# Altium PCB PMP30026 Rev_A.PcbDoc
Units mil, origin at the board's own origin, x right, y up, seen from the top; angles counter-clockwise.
Board outline 2370 x 2370 mil, 2 copper layers (Top Layer, Bottom Layer), stack 62 mil thick; 53 components, 28 nets, 107 pads, 37 vias.
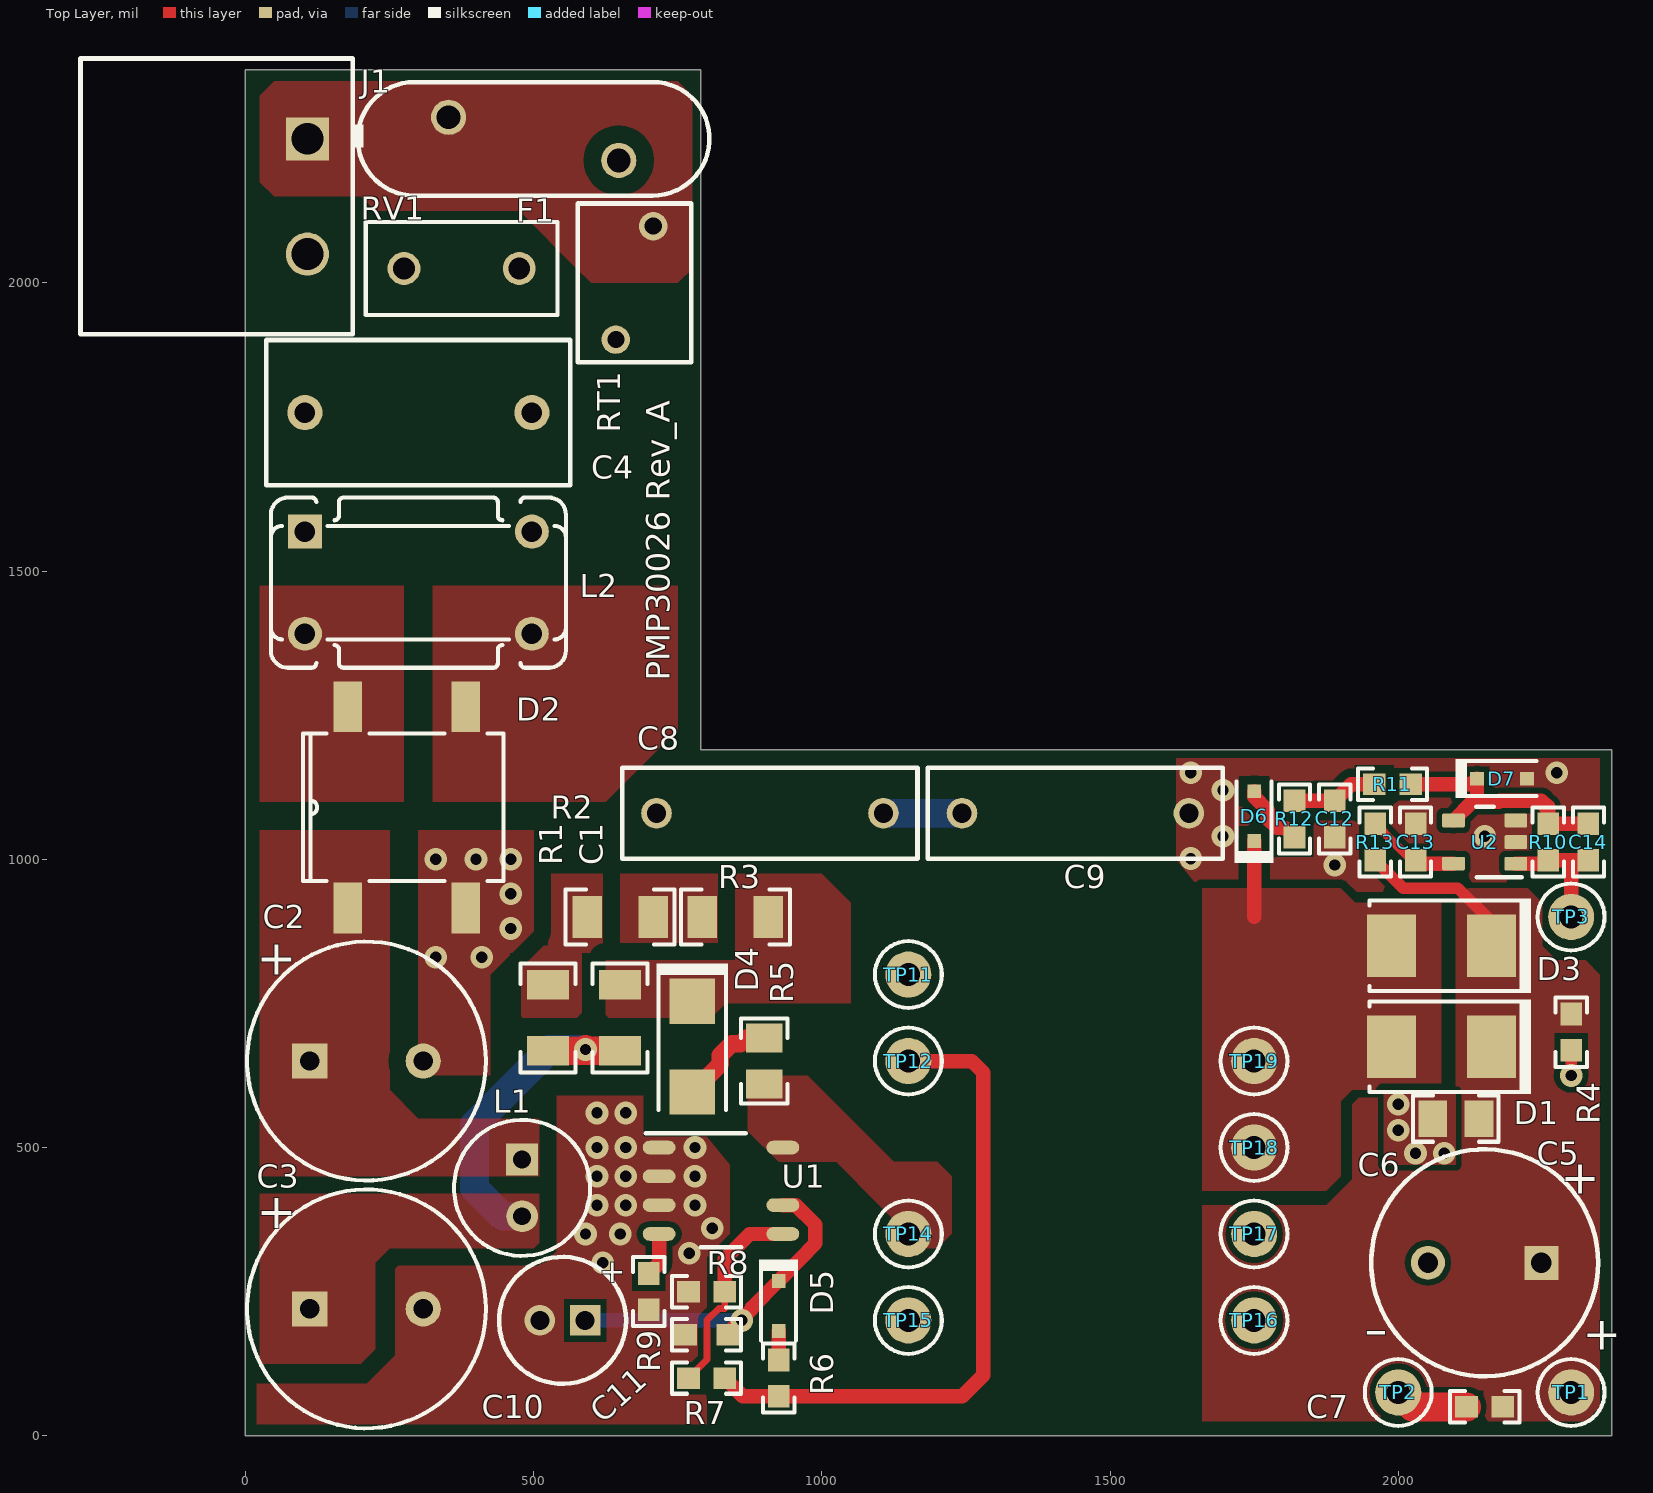
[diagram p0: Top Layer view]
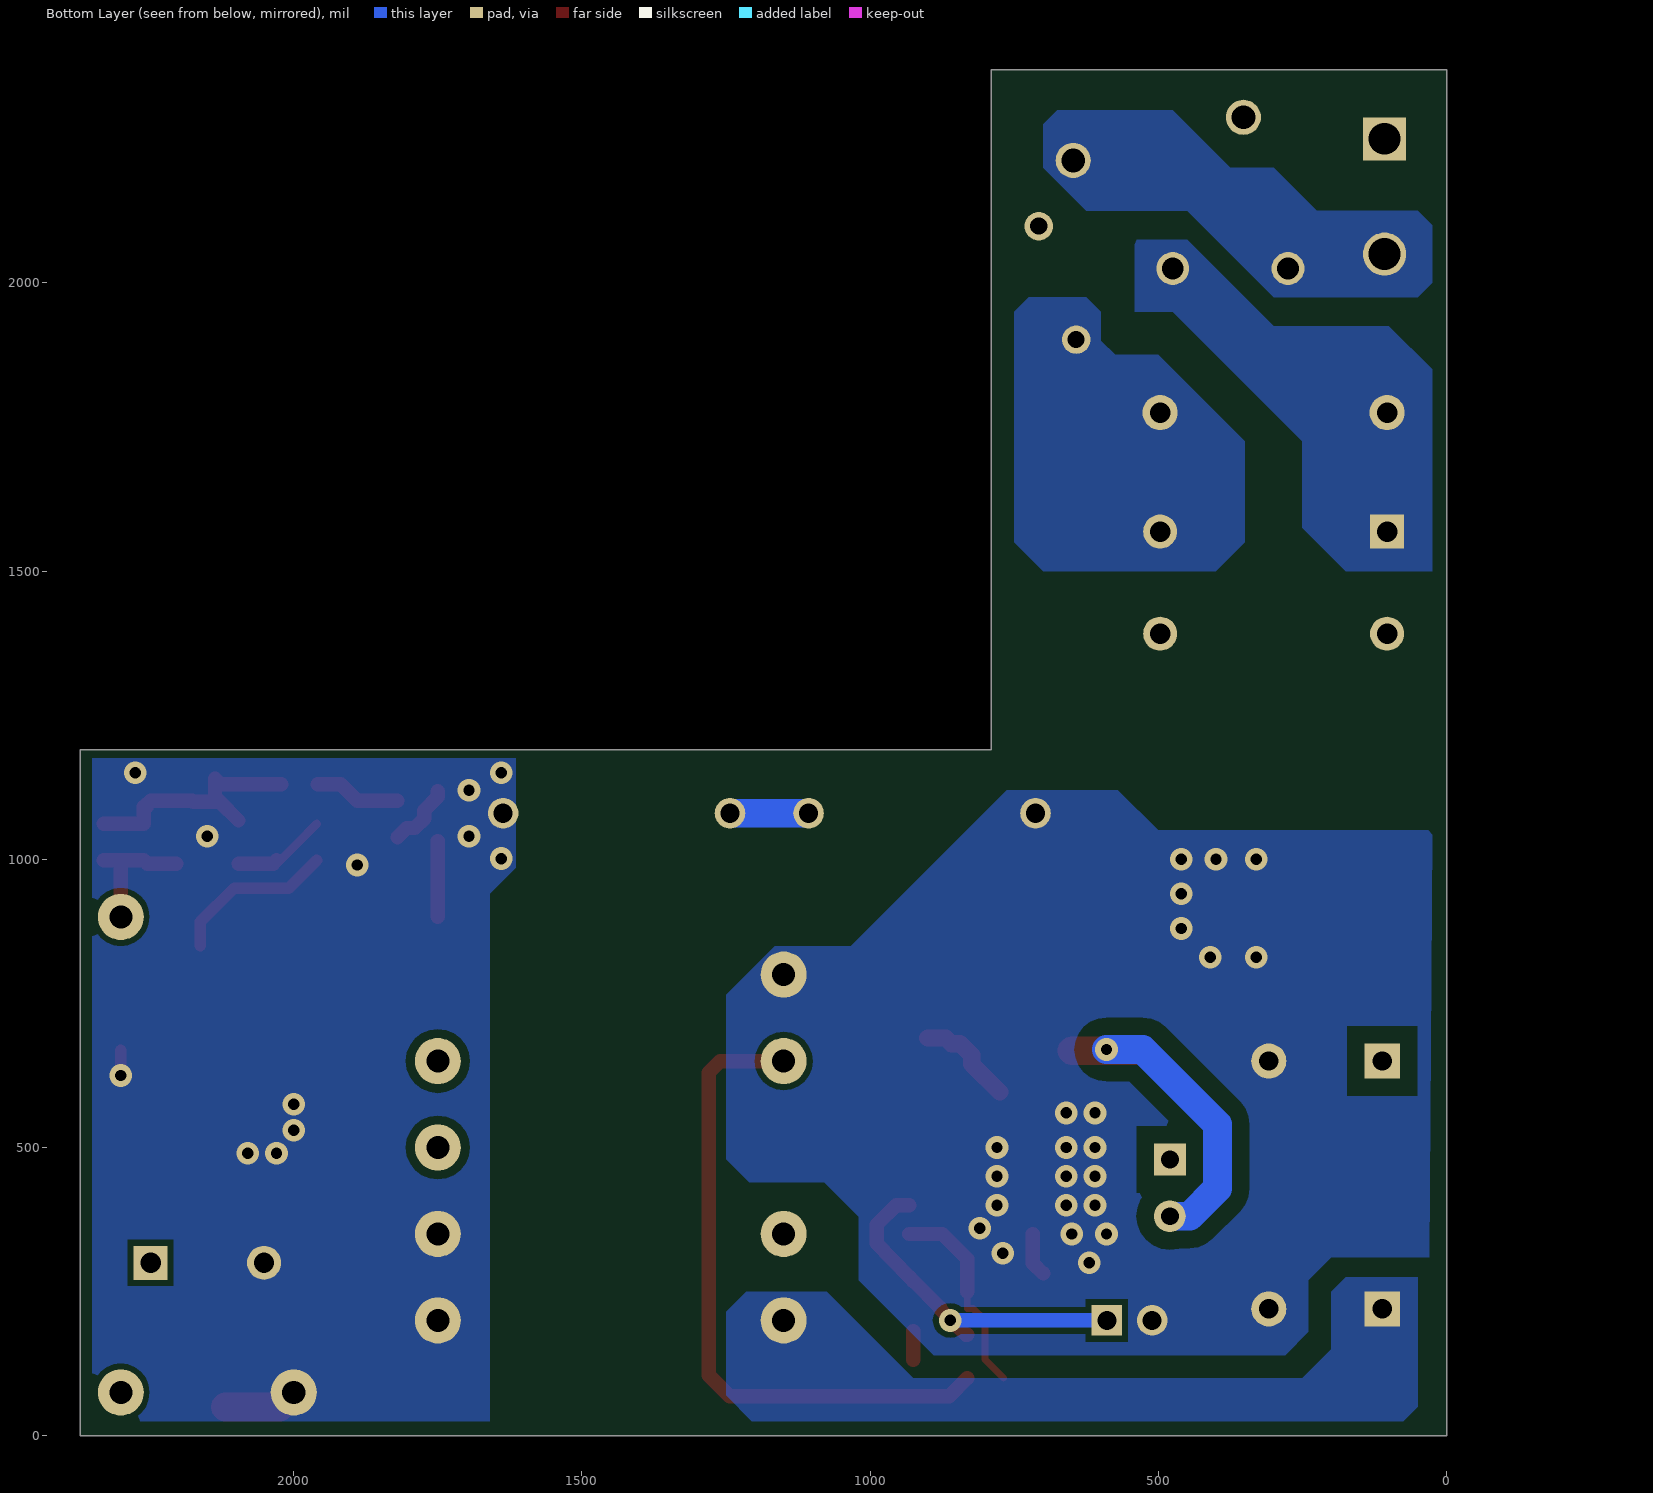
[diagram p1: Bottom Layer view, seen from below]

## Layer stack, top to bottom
Top Solder: solder mask 0.4, Solder Resist, Dk 3.5
Top Layer: signal copper 1.4
Dielectric1: core 59.2, CAM-1, Dk 4.8
Bottom Layer: signal copper 1.4
Bottom Solder: solder mask 0.4, Solder Resist, Dk 3.5

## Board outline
0,0 0,2370 790,2370 790,1190 2370,1190 2370,0

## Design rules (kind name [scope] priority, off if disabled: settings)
AcuteAngle [All] p1: minimum=4.50000000000000E+0001 checktracksonly=FALSE
AssemblyTestPointUsage [All] p1: valid=2
Clearance "Schematic Clearance Constraint_24" [InNet('NetR1_1')] p1: gap=30
Clearance "Schematic Clearance Constraint_23" [InNet('NetR2_1')] p2: gap=30
Clearance "Schematic Clearance Constraint_22" [InNet('NetF1_1')] p3: gap=30
Clearance "Schematic Clearance Constraint_21" [InNet('NetD2_4')] p4: gap=30
Clearance "Schematic Clearance Constraint_20" [InNet('NetD2_3')] p5: gap=30
Clearance "Schematic Clearance Constraint_19" [InNet('NetC4_2')] p6: gap=30
Clearance "Schematic Clearance Constraint_18" [InNet('NetC4_1')] p7: gap=30
Clearance "Schematic Clearance Constraint_17" [InNet('NetC2_1')] p8: gap=30
Clearance "Schematic Clearance Constraint_16" [InNet('NetC1_2')] p9: gap=30
Clearance "Schematic Clearance Constraint_14" [InNet('NetC1_1')] p10: gap=30
Clearance "Schematic Clearance Constraint_13" [InNet('NetD4_2')] p11: gap=30
Clearance "Schematic Clearance Constraint_11" [InNet('NetD6_2')] p12: gap=15
Clearance "Schematic Clearance Constraint_10" [InNet('NetC12_2')] p13: gap=15
Clearance "Schematic Clearance Constraint_9" [InNet('NetR9_2')] p14: gap=10
Clearance "Schematic Clearance Constraint_8" [InNet('NetR7_1')] p15: gap=10
Clearance "Schematic Clearance Constraint_7" [InNet('NetR6_1')] p16: gap=10
Clearance "Schematic Clearance Constraint_5" [InNet('NetC14_2')] p17: gap=10
Clearance "Schematic Clearance Constraint_4" [InNet('NetC14_1')] p18: gap=10
Clearance "Schematic Clearance Constraint_2" [InNet('NetC13_1')] p19: gap=10
Clearance "Schematic Clearance Constraint_1" [InNet('NetC10_1')] p20: gap=10
Clearance "Schematic Clearance Constraint" [InNet('NetC5_1')] p21: gap=10
Clearance "Schematic Clearance Constraint_6" [InNet('NetD1_2')] p22: gap=15
Clearance "Schematic Clearance Constraint_3" [InNet('NetD5_2')] p23: gap=10
Clearance "Schematic Clearance Constraint_15" [InNet('NetJ1_1')] p24: gap=30
Clearance "Schematic Clearance Constraint_12" [InNet('NetR5_1')] p25: gap=30
Clearance Clearance_Keepouts [((IsTrack Or IsArc) And Not InPoly) And IsFree and IsKeepOut vs ((IsTrack Or IsArc) And Not InPoly) And IsFree and IsKeepOut] p26: gap=0
Clearance Clearance_BoardEdge_MountingHoles [OnCopper and InComponentClass('Mounting Holes') vs IsKeepOut] p27: gap=40
Clearance Clearance_BoardEdge_Poly [OnCopper and InPoly vs IsKeepOut] p28: gap=25
Clearance Clearance_BoardEdge [OnCopper and Not InComponentClass('Logo') and not InComponentClass('FiducialMark') and not InRegion(1000,500,4000,800) and Not IsKeepout vs IsKeepOut] p29: gap=75
Clearance Clearance_Poly [InPolygon] p30: gap=25
Clearance [All] p31: gap=7.87
ComponentClearance ComponentClearance_MountingHoles_FiducialMarks [InComponentClass('Mounting Holes') vs InComponentClass('FiducialMark')] p1: gap=10 collisioncheckmode=3 verticalgap=10 showdistances=FALSE
ComponentClearance ComponentClearance_Shunt [InComponentClass('Header') vs InComponentClass('Shunt')] p2: gap=0 collisioncheckmode=3 verticalgap=0 showdistances=FALSE
ComponentClearance ComponentClearance_Logo [InComponentClass('Logo')] p3: gap=50 collisioncheckmode=3 verticalgap=10 showdistances=FALSE
ComponentClearance ComponentClearance_ScrewToNut [(HasFootprint('NY PMS 440 0025 PH')) vs (HasFootprint('Keystone_1902C'))] p4: gap=5 collisioncheckmode=3 verticalgap=10 showdistances=FALSE
ComponentClearance ComponentClearance_MountingHoles [InComponentClass('Mounting Holes')] p5: gap=250 collisioncheckmode=3 verticalgap=100000 showdistances=FALSE
ComponentClearance ComponentClearance_SmallPassives [HasFootprint('0201*') or HasFootprint('0402*') or HasFootprint('0508') or HasFootprint('0603*') or HasFootprint('0612') or HasFootprint('0805*') or HasFootprint('0815*') or HasFootprint('0830*') or HasFootprint('1206*') or HasFootprint('1210*') or HasFootprint('1808*') or HasFootprint('1812*') or HasFootprint('1825*') or HasFootprint('2010*') or HasFootprint('2220*') or HasFootprint('2225*') or HasFootprint('2512*') or HasFootprint('2728*') or HasFootprint('3518*') vs HasFootprint('0201*') or HasFootprint('0402*') or HasFootprint('0508') or HasFootprint('0603*') or HasFootprint('0612') or HasFootprint('0805*') or HasFootprint('0815*') or HasFootprint('0830*') or HasFootprint('1206*') or HasFootprint('1210*') or HasFootprint('1808*') or HasFootprint('1812*') or HasFootprint('1825*') or HasFootprint('2010*') or HasFootprint('2220*') or HasFootprint('2225*') or HasFootprint('2512*') or HasFootprint('2728*') or HasFootprint('3518*')] p6: gap=20 collisioncheckmode=3 verticalgap=10 showdistances=FALSE
ComponentClearance ComponentClearance_THtoSMT [IsThruComponent vs IsSMTComponent] p7: gap=20 collisioncheckmode=3 verticalgap=20 showdistances=FALSE
ComponentClearance ComponentClearance_THtoTH [IsThruComponent vs IsThruComponent] p8: gap=10 collisioncheckmode=3 verticalgap=30 showdistances=FALSE
ComponentClearance [All] p9: gap=20 collisioncheckmode=3 verticalgap=10 showdistances=FALSE
DiffPairsRouting [All] p1: maxlimit=100 minlimit=10 mostfreqgap=10 toplayer_minwidth=15 toplayer_maxwidth=15 toplayer_prefwidth=15 bottomlayer_minwidth=15 bottomlayer_maxwidth=15 bottomlayer_prefwidth=15 maxuncoupledlength=1000
FabricationTestPointUsage TestPointUsage [All] p1: valid=2 allowmultiple=FALSE
FabricationTestpoint Testpoint [All] p1: side=3 testpointundercomponent=TRUE minsize=40 maxsize=100 preferedsize=60 minholesize=0 maxholesize=40 preferedholesize=32 testpointgrid=1 allowsidetop=TRUE allowsidebottom=TRUE usegrid=TRUE gridtolerance=0.01
FanoutControl Fanout_LCC [IsLCC] p1: bgadir=Out bgaviamode=Centered fanoutstyle=Auto fanoutdirection=Alternating viagrid=1 // Fanout_LCC (Default Rule)
FanoutControl Fanout_BGA [IsBGA] p2: bgadir=Out bgaviamode=Centered fanoutstyle=Auto fanoutdirection=Alternating viagrid=1 // Fanout_BGA (Default Rule)
FanoutControl Fanout_Default [All] p4: bgadir=Out bgaviamode=Centered fanoutstyle=Auto fanoutdirection=Alternating viagrid=1 // Fanout_Default (Default Rule)
FanoutControl Fanout_Small [(CompPinCount < 5)] p5: bgadir=Out bgaviamode=Centered fanoutstyle=Auto fanoutdirection=OutThenIn viagrid=1 // Fanout_Small (Default Rule)
HoleSize [All] p1: absolutevalues=TRUE maxlimit=251 minlimit=8 maxpercent=80.000 minpercent=20.000
MinimumAnnularRing MinimumAnnularRing_ThermalPadVias [IsVia and InAnyComponent] p1: minimumring=5.91
MinimumAnnularRing [All] p2: minimumring=9
MinimumSolderMaskSliver MinimumSolderMaskSliver_Logo [InComponentClass('Logo') vs InComponentClass('Logo')] p1: minsoldermaskwidth=0.7
MinimumSolderMaskSliver [All] p2: minsoldermaskwidth=3.94
PlaneConnect [All] p1: planeconnectstyle=Relief reliefexpansion=10 reliefentries=4 reliefconductorwidth=10 reliefairgap=10
PolygonConnect PolygonConnect_33 [All vs IsNamedPolygon('NETR2_1_L01_P032')] p1: connectstyle=Direct reliefconductorwidth=10 reliefentries=4 polygonreliefangle="90 Angle" airgapwidth=10
PolygonConnect PolygonConnect_32 [All vs IsNamedPolygon('NETR1_1_L01_P034')] p2: connectstyle=Direct reliefconductorwidth=10 reliefentries=4 polygonreliefangle="90 Angle" airgapwidth=10
PolygonConnect PolygonConnect_31 [All vs IsNamedPolygon('NETC2_1_L01_P014')] p3: connectstyle=Direct reliefconductorwidth=10 reliefentries=4 polygonreliefangle="90 Angle" airgapwidth=10
PolygonConnect PolygonConnect_30 [All vs IsNamedPolygon('NETC1_2_L01_P030')] p4: connectstyle=Direct reliefconductorwidth=10 reliefentries=4 polygonreliefangle="90 Angle" airgapwidth=10
PolygonConnect PolygonConnect_29 [All vs IsNamedPolygon('NETC1_1_L01_P016')] p5: connectstyle=Direct reliefconductorwidth=10 reliefentries=4 polygonreliefangle="90 Angle" airgapwidth=10
PolygonConnect PolygonConnect_28 [All vs IsNamedPolygon('GND_L01_P026')] p6: connectstyle=Direct reliefconductorwidth=10 reliefentries=4 polygonreliefangle="90 Angle" airgapwidth=10
PolygonConnect PolygonConnect_27 [All vs IsNamedPolygon('S-GND_L01_P042')] p7: connectstyle=Direct reliefconductorwidth=10 reliefentries=4 polygonreliefangle="90 Angle" airgapwidth=10
PolygonConnect PolygonConnect_26 [All vs IsNamedPolygon('S-GND_L02_P040')] p8: connectstyle=Direct reliefconductorwidth=10 reliefentries=4 polygonreliefangle="90 Angle" airgapwidth=10
PolygonConnect PolygonConnect_25 [All vs IsNamedPolygon('NETC5_1_L01_P038')] p9: connectstyle=Direct reliefconductorwidth=10 reliefentries=4 polygonreliefangle="90 Angle" airgapwidth=10
PolygonConnect PolygonConnect_24 [All vs IsNamedPolygon('NETD1_2_L01_P036')] p10: connectstyle=Direct reliefconductorwidth=10 reliefentries=4 polygonreliefangle="90 Angle" airgapwidth=10
PolygonConnect PolygonConnect_23 [All vs IsNamedPolygon('S-GND_L01_P000')] p11: connectstyle=Direct reliefconductorwidth=10 reliefentries=4 polygonreliefangle="90 Angle" airgapwidth=10
PolygonConnect PolygonConnect_22 [All vs IsNamedPolygon('S-GND_L01_P038')] p12: connectstyle=Direct reliefconductorwidth=10 reliefentries=4 polygonreliefangle="90 Angle" airgapwidth=10
PolygonConnect PolygonConnect_21 [All vs IsNamedPolygon('NETC5_1_L01_P036')] p13: connectstyle=Direct reliefconductorwidth=10 reliefentries=4 polygonreliefangle="90 Angle" airgapwidth=10
PolygonConnect PolygonConnect_20 [All vs IsNamedPolygon('NETD1_2_L01_P034')] p14: connectstyle=Direct reliefconductorwidth=10 reliefentries=4 polygonreliefangle="90 Angle" airgapwidth=10
PolygonConnect PolygonConnect_19 [All vs IsNamedPolygon('NETR1_1_L01_P032')] p15: connectstyle=Direct reliefconductorwidth=10 reliefentries=4 polygonreliefangle="90 Angle" airgapwidth=10
PolygonConnect PolygonConnect_18 [All vs IsNamedPolygon('NETR2_1_L01_P030')] p16: connectstyle=Direct reliefconductorwidth=10 reliefentries=4 polygonreliefangle="90 Angle" airgapwidth=10
PolygonConnect PolygonConnect_17 [All vs IsNamedPolygon('NETC1_2_L01_P028')] p17: connectstyle=Direct reliefconductorwidth=10 reliefentries=4 polygonreliefangle="90 Angle" airgapwidth=10
PolygonConnect PolygonConnect_16 [All vs IsNamedPolygon('GND_L02_P028')] p18: connectstyle=Direct reliefconductorwidth=10 reliefentries=4 polygonreliefangle="90 Angle" airgapwidth=10
PolygonConnect PolygonConnect_15 [All vs IsNamedPolygon('GND_L01_P024')] p19: connectstyle=Direct reliefconductorwidth=10 reliefentries=4 polygonreliefangle="90 Angle" airgapwidth=10
PolygonConnect PolygonConnect_14 [All vs IsNamedPolygon('GND_L01_P020')] p20: connectstyle=Direct reliefconductorwidth=10 reliefentries=4 polygonreliefangle="90 Angle" airgapwidth=10
PolygonConnect PolygonConnect_13 [All vs IsNamedPolygon('NETR5_1_L01_P020')] p21: connectstyle=Direct reliefconductorwidth=10 reliefentries=4 polygonreliefangle="90 Angle" airgapwidth=10
PolygonConnect PolygonConnect_12 [All vs IsNamedPolygon('NETC1_1_L02_P018')] p22: connectstyle=Direct reliefconductorwidth=10 reliefentries=4 polygonreliefangle="90 Angle" airgapwidth=10
PolygonConnect PolygonConnect_11 [All vs IsNamedPolygon('NETC1_1_L01_P014')] p23: connectstyle=Direct reliefconductorwidth=10 reliefentries=4 polygonreliefangle="90 Angle" airgapwidth=10
PolygonConnect PolygonConnect_10 [All vs IsNamedPolygon('NETC2_1_L01_P012')] p24: connectstyle=Direct reliefconductorwidth=10 reliefentries=4 polygonreliefangle="90 Angle" airgapwidth=10
PolygonConnect PolygonConnect_9 [All vs IsNamedPolygon('NETD2_3_L01_P012')] p25: connectstyle=Direct reliefconductorwidth=10 reliefentries=4 polygonreliefangle="90 Angle" airgapwidth=10
PolygonConnect PolygonConnect_8 [All vs IsNamedPolygon('NETD2_4_L01_P010')] p26: connectstyle=Direct reliefconductorwidth=10 reliefentries=4 polygonreliefangle="90 Angle" airgapwidth=10
PolygonConnect PolygonConnect_7 [All vs IsNamedPolygon('NETJ1_1_L01_P008')] p27: connectstyle=Direct reliefconductorwidth=10 reliefentries=4 polygonreliefangle="90 Angle" airgapwidth=10
PolygonConnect PolygonConnect_6 [All vs IsNamedPolygon('NETF1_1_L02_P006')] p28: connectstyle=Direct reliefconductorwidth=10 reliefentries=4 polygonreliefangle="90 Angle" airgapwidth=10
PolygonConnect PolygonConnect_5 [All vs IsNamedPolygon('NETC4_2_L02_P004')] p29: connectstyle=Direct reliefconductorwidth=10 reliefentries=4 polygonreliefangle="90 Angle" airgapwidth=10
PolygonConnect PolygonConnect_4 [All vs IsNamedPolygon('NETC4_1_L02_P002')] p30: connectstyle=Direct reliefconductorwidth=10 reliefentries=4 polygonreliefangle="90 Angle" airgapwidth=10
PolygonConnect PolygonConnect_3 [All vs IsNamedPolygon('D2_1') Or  IsNamedPolygon('GND2') Or  IsNamedPolygon('GND') Or  IsNamedPolygon('C1_2') Or  IsNamedPolygon('C2_2') Or  IsNamedPolygon('C5_1')] p31: connectstyle=Direct reliefconductorwidth=10 reliefentries=4 polygonreliefangle="90 Angle" airgapwidth=10
PolygonConnect PolygonConnect_2 [All vs IsNamedPolygon('C5_1') Or  IsNamedPolygon('C1_2') Or  IsNamedPolygon('GND') Or  IsNamedPolygon('C2_2') Or  IsNamedPolygon('D2_1')] p32: connectstyle=Direct reliefconductorwidth=10 reliefentries=4 polygonreliefangle="90 Angle" airgapwidth=10
PolygonConnect PolygonConnect_1 [All vs IsNamedPolygon('C2_2') Or  IsNamedPolygon('D2_1') Or  IsNamedPolygon('C1_2') Or  IsNamedPolygon('C5_1')] p33: connectstyle=Direct reliefconductorwidth=10 reliefentries=4 polygonreliefangle="90 Angle" airgapwidth=10
PolygonConnect [All] p34: connectstyle=Relief reliefconductorwidth=10 reliefentries=4 polygonreliefangle="90 Angle" airgapwidth=10
RoutingVias ThermalPadVias [IsVia and InAnyComponent] p1: holewidth=7.87 width=19.68 viastyle="Through Hole" minholewidth=7.87 minwidth=19.68 maxholewidth=12.99 maxwidth=23.62
RoutingVias [All] p2: holewidth=16 width=34 viastyle="Through Hole" minholewidth=7.87 minwidth=26 maxholewidth=40 maxwidth=65
SilkToBoardRegionClearance [Not ((IsComment or IsDesignator) And (Hide <> 'False')) and not InRegion(1000,500,4000,800)] p1:
SilkToSilkClearance SilkToSilkClearance_Pb-FreeLogo [(HasFootprint('Pb-Free_Overlay_Medium') OR HasFootprint('Pb-Free_Overlay_Small')) vs (HasFootprint('Pb-Free_Overlay_Medium') OR HasFootprint('Pb-Free_Overlay_Small'))] p1: silktosilkclearance=0
SilkToSilkClearance [All] p2: silktosilkclearance=5
SilkToSolderMaskClearance "Silk to Solder Mask Opening" [All] p1: minsilkscreentomaskgap=1 clearancetoexposedcopper=FALSE
SolderMaskExpansion [All] p1: expansion=1.97
Width [All] p1: maxlimit=100 minlimit=6 preferedwidth=10 checkconnectedcopper=TRUE
15 further rules are at their usual default settings.

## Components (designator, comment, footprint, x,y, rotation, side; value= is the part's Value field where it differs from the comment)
C1 "C3216X7R2J472K" 1206 650,725 r90 top
C2 "UVC2G150MPD" EE_1000x2000 210,650 r0 top
C3 "UVC2G150MPD" EE_1000x2000 210,220 r0 top
C4 "R46KF310000P1M" R46_1300x1200x600 300,1775 r0 top
C5 "16ZLJ1000MCE10X16" CAPPR5-10x16 2150,300 r180 top
C6 "GRM21BR61E226ME44L" 0805_HV 2100,550 r180 top
C7 "C1608X7R1H104K" 0603#1 2150,50 r180 top
C8 "R413F12200000M" PHE850_1300x400x900 910,1080 r180 top
C9 "R413F12200000M" PHE850_1300x400x900 1440,1080 r180 top
C10 "EEU-FM1E470" FM_500x1100 550,200 r180 top
C11 "C1608X7R1H104K" 0603#2 800,175 r180 top
C12 "GRM188R72A104KA35D" 0603#1 1890,1070 r90 top
C13 "C1608X7R1H104K" 0603#1 2030,1030 r90 top
C14 "C1608X7R1H104K" 0603#1 2330,1030 r270 top
D1 "ES2D-13-F" SMB 2075,675 r180 top
D2 "DI156S" DF-S 280,1090 r90 top
D3 "ES2D-13-F" SMB 2075,850 r180 top
D4 "US1J-13-F" SMA 775,675 r270 top
D5 "BAS20HT1G" sod-323 925,225 r270 top
D6 "BAS20HT1G" sod-323 1750,1075 r90 top
D7 "BAT46WJ,115" SOD-323F 2180,1140 r0 top
F1 "RST 1-BULK" Fuse_RST 375,2025 r0 top
J1 "CIM029P5" PHOENIX_1757242 -50,2150 r270 top
L1 "7447462102" WE-TI_5075 480,430 r270 top
L2 "744821120" WE-CMB_XS 300,1480 r0 top
R1 "CRCW120647K0JNEA" 1206 525,725 r270 top
R2 "CRCW120647K0JNEA" 1206 650,900 r180 top
R3 "CRCW120647K0JNEA" 1206 850,900 r0 top
R4 "CRCW060318K2FKEA" 0603#1 2300,700 r90 top
R5 "CRCW080547R5FKEA" 0805_HV 900,650 r90 top
R6 "CRCW060315R0FKEA" 0603#1 925,100 r90 top
R7 "CRCW060373K2FKEA" 0603#1 800,100 r0 top
R8 "CRCW060326K1FKEA" 0603#1 800,250 r0 top
R9 "CRCW06031K00FKEA" 0603#1 700,250 r90 top
R10 "CRCW06036K49FKEA" 0603#1 2260,1030 r270 top
R11 "CRCW0603100KFKEA" 0603#1 1990,1130 r0 top
R12 "CRCW0603100RFKEA" 0603#1 1820,1070 r90 top
R13 "CRCW0603100RFKEA" 0603#1 1960,1030 r270 top
RT1 "MF72-005D5" MF72D5 675,2000 r270 top
RV1 "B72214S271K101" TDK_B72214S2211K101 500,2250 r180 top
TP1 "5000" Keystone5000 2300,75 r90 top
TP2 "5001" Keystone5001 2000,75 r90 top
TP3 "5002" Keystone5002 2300,900 r90 top
TP11 "5000" Keystone5000 1150,800 r0 top
TP12 "5000" Keystone5000 1150,650 r0 top
TP14 "5000" Keystone5000 1150,350 r0 top
TP15 "5000" Keystone5000 1150,200 r0 top
TP16 "5000" Keystone5000 1750,200 r0 top
TP17 "5000" Keystone5000 1750,350 r0 top
TP18 "5000" Keystone5000 1750,500 r0 top
TP19 "5000" Keystone5000 1750,650 r0 top
U1 "UCC28911DR" D0007A_N 825,425 r0 top
U2 "TS321IDBVR" DBV0005A_N 2150,1030 r180 top

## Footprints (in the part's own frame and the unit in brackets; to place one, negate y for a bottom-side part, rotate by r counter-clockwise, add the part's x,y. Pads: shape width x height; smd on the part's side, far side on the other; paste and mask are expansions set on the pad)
0603#1 [mm] "0603 from SM-752 data"
  rect 1x0.95 smd: 1(-0.8,0) 2(0.8,0)
  silkscreen extent -1.52,-0.69 1.52,0.69, body extent -0.87,-0.47 0.87,0.47, height 1
0603#2 [mm] "0603 from SM-752 data"
  rect 1x0.95 smd: 1(-0.927,0) 2(0.927,0)
  silkscreen extent -1.52,-0.69 1.52,0.69, body extent -0.87,-0.47 0.87,0.47, height 1
0805_HV [mil] "0805 with 30mil clearance between pads"
  rect 50x63 smd: 1(-40,0) 2(40,0)
  silkscreen extent -74,-40 74,40, body extent -43,-29 43,29, height 57
1206 [mm] "1206 from SM-752 data"
  rect 1.3x1.85 smd: 1(-1.45,0) 2(1.45,0)
  silkscreen extent -2.4,-1.21 2.4,1.21, body extent -1.7,-0.9 1.7,0.9, height 1.35
CAPPR5-10x16 [mm] "Capacitor, Electrolytic, Radial; Body 10 x 16 mm (Dia.xH typ); Pin Spacing 5 mm (typ)"
  rect 1.5x1.5 hole 0.9: 1(-2.5,0)
  round 1.5 hole 0.9: 2(2.5,0)
  silkscreen extent -5,-5 5,5, body extent -5.03,-5.03 5.03,5.02, height 16.29
D0007A_N [mm] "SOIC, 7-Leads, Body 4.9x3.9mm, Pitch 1.27mm, IPC Medium Density"
  oval 1.45x0.6 smd: 1(-2.725,1.905) 2(-2.725,0.635) 3(-2.725,-0.635) 4(-2.725,-1.905) 5(2.725,-1.905) 6(2.725,-0.635) 8(2.725,1.905)
  silkscreen extent -3.32,-2.5 1.1,2.52, body extent -3.01,-2.45 3.01,2.45, height 1.75
DBV0005A_N [mm] "SOT23, 5-Leads, Body 2.9x1.6mm, Pitch 0.95mm, Lead Span 2.8mm, IPC Medium Density"
  rrect17% 1x0.6 smd: 1(-1.375,0.95) 2(-1.375,0) 3(-1.375,-0.95) 4(1.375,-0.95) 5(1.375,0.95)
  silkscreen extent -1.63,-1.55 0.38,1.55, body extent -1.42,-1.46 1.42,1.46, height 1.09
DF-S [mil] "Diodes Inc. recommended land pattern per ap02001.pdf rev 30"
  rect 88x49 smd: 1(-174.5,102.36) 2(-174.5,-102.36) 3(174.5,-102.36) 4(174.5,102.36)
  silkscreen extent -128,-168 128,180, body extent -205,-168 205,168, height 108
EE_1000x2000 [mm] "PANASONIC"
  rect 1.55x1.55 hole 0.85: 1(-2.5,0)
  round 1.55 hole 0.85: 2(2.5,0)
  silkscreen extent -5.26,-5.26 5.26,5.26, body extent -5.21,-5.24 5.24,5.24, height 22.01
FM_500x1100 [mm] "PANASONIC"
  rect 1.35x1.35 hole 0.838: 1(-1,0)
  round 1.35 hole 0.838: 2(1,0)
  silkscreen extent -2.8,-2.8 2.8,2.8, body extent -2.73,-2.75 2.75,2.75, height 12.51
Fuse_RST [mm] "Bel Fuse RST series May2012D"
  round 1.45 hole 0.95: 1(-2.54,0) 2(2.54,0)
  silkscreen extent -4.23,-2.05 4.23,2.05, body extent -4.22,-2.05 4.23,2.05, height 7.9
Keystone5000 [mil] "For Keystone 500x miniature loop terminals"
  round 80 hole 40: 1(0,0)
  silkscreen extent -58,-58 58,58, body extent -49,-49 49,49, height 182
Keystone5001 [mil] "For Keystone 500x miniature loop terminals"
  round 80 hole 40: 1(0,0)
  silkscreen extent -58,-58 58,58, body extent -49,-49 49,49, height 182
Keystone5002 [mil] "For Keystone 500x miniature loop terminals"
  round 80 hole 40: 1(0,0)
  silkscreen extent -58,-58 58,58, body extent -49,-49 49,49, height 182
MF72D5 [mm] "TH, 2-Leads, Dia 7mm"
  round 1.25 hole 0.75: 1(-2.5,0.825) 2(2.5,-0.825)
  silkscreen extent -3.5,-2.5 3.5,2.5, body extent -3.52,-2.5 3.48,2.5, height 11
PHE850_1300x400x900 [mm] "TH, 2-Leads, Body 13x4mm, Lead Spacing 10mm"
  round 1.35 hole 0.85: 1(-5,0) 2(5,0)
  silkscreen extent -6.5,-2 6.5,2, body extent -6.5,-2 6.5,2, height 9
PHOENIX_1757242 [mm] "Header, 5.08 mm, 2x1, R/A, TH"
  rect 1.9x1.9 hole 1.4: 1(-2.54,4)
  round 1.9 hole 1.4: 2(2.54,4)
  silkscreen extent -6.08,-6 6.08,6.47, body extent -6.06,-6.02 6.1,5.98, height 8.6
R46_1300x1200x600 [mm] "KEMET"
  round 1.55 hole 0.9: 1(-5,0) 2(5,0)
  silkscreen extent -6.7,-3.2 6.7,3.2, body extent -6.6,-3.1 6.6,3.1, height 12.1
SMA [mm] "Molded Diode, 2-Leads, Body 4.3x2.6mm, IPC Medium Density, based on OnSemi component dimensions and land pattern"
  rect 2x2 smd: 1(-2,0) 2(2,0)
  silkscreen extent -3.66,-1.57 2.79,1.57, body extent -2.6,-1.3 2.6,1.3, height 2.42
SMB [mil] "Molded Diode, 2-Leads, Body 5.4x3.6mm, IPC Medium Density, based on OnSemi component dimensions"
  rect 85x107.99 smd: 1(-87.01,0) 2(87.01,0)
  silkscreen extent -155,-82 125,82, body extent -106,-71 106,71, height 91
sod-323 [mm] "NXP recommended land pattern"
  rect 0.6x0.6 smd paste-0.05: 1(-1.1,0) 2(1.1,0)
  silkscreen extent -2.06,-0.86 1.53,0.86, body extent -1.3,-0.67 1.3,0.68, height 1.1
SOD-323F [mm] "NXP recommended land pattern"
  rect 0.6x0.6 smd paste-0.05: 1(-1.1,0) 2(1.1,0)
  silkscreen extent -2.06,-0.86 1.53,0.86, body extent -1.35,-0.67 1.35,0.68, height 0.79
TDK_B72214S2211K101 [mm] "TH, 2-Leads, Body 15.5x5mm, Pin Spacing 7.5mm"
  round 1.55 hole 1.05: 1(-3.75,0.95) 2(3.75,-0.95)
  silkscreen extent -7.75,-2.5 7.75,2.5, body extent -7.69,-2.5 7.75,2.5, height 18.48
WE-CMB_XS [mm] "WE-CMB Series Size XS"
  rect 1.5x1.5 hole 0.9: 1(-5,2.25)
  round 1.5 hole 0.9: 2(-5,-2.25) 3(5,-2.25) 4(5,2.25)
  silkscreen extent -6.5,-3.75 6.5,3.75, body extent -6.5,-3.75 6.5,3.75, height 16.24
WE-TI_5075 [mm] "Wurth WE-TI 5075"
  rect 1.4x1.4 hole 0.787: 1(-1.25,0)
  round 1.4 hole 0.787: 2(1.25,0)
  silkscreen extent -3,-3 3,3, body extent -3,-3 3,3, height 8.5

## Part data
C1: "CAP, CERM, 4700 pF, 630 V, +/- 10%, X7R, 1206"
C2 C3: library part EEU-EE2E220, "CAP, AL, 15 µF, 400 V, +/- 20%, TH"
C4: library part R46KF310050P0K, "CAP, Film, 0.1 µF, 275 Vac, +/- 20%, TH"
C5: "CAP, AL, 1000 µF, 16 V, +/- 20%, TH"
C6: "CAP, CERM, 22 µF, 25 V, +/- 20%, X5R, 0805"
C7 C11 C13 C14: "CAP, CERM, 0.1 µF, 50 V, +/- 10%, X7R, 0603"
C8 C9: library part PHE850EA4220MA01R17, "CAP, Film, 2200 pF, 300 VAC, Class Y2, R41 +/- 20%, TH"
C10: "CAP, AL, 47 µF, 25 V, +/- 20%, 0.3 ohm, TH"
C12: "CAP, CERM, 0.1 µF, 100 V, +/- 10%, X7R, 0603"
D1 D3: "Diode, Ultrafast, 200 V, 2 A, SMB"
D2: library part DF08SA, "Diode, Bridge, 600 V, 1.5 A"
D4: "Diode, Ultrafast, 600 V, 1 A, SMA"
D5 D6: library part BAS316,115, "DIODE SWITCH 200V 200MA SOD323"
D7: "Diode, Schottky, 100 V, 0.25 A, SOD-323F"
F1: library part "RST 500", "FUSE BOARD MOUNT 1A 250VAC RAD"
J1: library part 1757242, "Header (Shrouded), 5.08 mm, 2x1, Tin, R/A, TH"
L1: "Inductor, Unshielded Drum Core, Ferrite, 1 mH, 0.25 A, 4.38 ohm, TH"
L2: "Coupled inductor, 20 mH, 0.5 A, 1 ohm, TH"
R1 R2 R3: "RES, 47 k, 5%, 0.25 W, 1206"
R4: "RES, 18.2 k, 1%, 0.1 W, 0603"
R5: "RES, 47.5, 1%, 0.125 W, 0805"
R6: "RES, 15.0 ohm, 1%, 0.1W, 0603"
R7: "RES, 73.2 k, 1%, 0.1 W, 0603"
R8: "RES, 26.1 k, 1%, 0.1 W, 0603"
R9: "RES, 1.00 k, 1%, 0.1 W, 0603"
R10: "RES, 6.49 k, 1%, 0.1 W, 0603"
R11: "RES, 100 k, 1%, 0.1 W, 0603"
R12 R13: "RES, 100, 1%, 0.1 W, 0603"
RT1: "Thermistor NTC, 5 ohm, 20%, MF72D5 TH"
RV1: library part B72214S2211K101, "VARISTOR 275Vac 6KA DISC 14MM"
TP1 TP11 TP12 TP14 TP15 TP16 TP17 TP18 TP19: "Test Point, Miniature, Red, TH"
TP2: "Test Point, Miniature, Black, TH"
TP3: "Test Point, Miniature, White, TH"
U1: "High Voltage Flyback Switcher with Primary-side Regulation and Constant-Current Control, D0007A"
U2: "Low-Power Single Operational Amplifier, 3 to 30 V, -40 to 125 degC, 5-pin SOT23 (DBV0005A), Green (RoHS & no Sb/Br)"

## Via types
v1: diameter 39.37, hole 19.68, Top Layer to Bottom Layer, 37 vias

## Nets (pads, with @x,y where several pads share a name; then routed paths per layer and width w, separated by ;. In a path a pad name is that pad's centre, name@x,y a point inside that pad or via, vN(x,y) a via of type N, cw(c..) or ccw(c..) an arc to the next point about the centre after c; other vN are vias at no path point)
GND: C2.2 C3.2 C8.2 C10.2 C11.2 D2.2 R8.1 R9.1 TP11.1 U1.1 U1.2 U1.3
  other v1: 620,300 770,316.73 590,350 650,350 810,360 610,400 660,400 780,400 610,450 660,450 780,450 610,500 660,500 780,500 610,560 660,560 330,830 410,830 460,880 460,940 330,1000 400,1000 460,1000
NetC1_1: C1.1 C3.1 L1.2 R1.2 TP15.1 | length 586.9
  Top Layer w50: R1.2 587.91,667.91 v1(590,670) 592.09,667.91 C1.1
  Bottom Layer w50: L1.2 445.53,380.79 397.44,428.87 397.44,540.27 408.16,550.98 408.16,551.07 527.09,670 v1(590,670)
NetC1_2: C1.2 D4.1 R3.2
NetC2_1: C2.1 D2.1 L1.1
NetC4_1: C4.1 F1.2 L2.1
NetC4_2: C4.2 L2.4 RT1.2
NetC5_1: C5.1 C6.1 C7.1 D1.1 D3.1 R4.2 R13.2 TP1.1 | length 287.8
  Top Layer w20: R13.2 2008.5,950 2103.5,950 2162.01,891.49 D3.1
NetC8_1: C8.1 C9.2 | length 136.3
  Bottom Layer w50: C8.1 C9.2
NetC10_1: C10.1 C11.1 D5.1 U1.6 | length 598.8
  Top Layer w25: C11.1@831.5,175 833.77,175 878.68,219.91 878.68,222.18 924.8,268.31 D5.1 932.28,275.59 988.33,333.72 988.33,366.28 954.61,400 U1.6
  Bottom Layer w25: C10.1 v1(861.02,200)
NetC12_2: C12.2 R11.1 R12.2 | length 150.3
  Top Layer w25: R12.2 C12.2 1918.5,1130 R11.1
NetC13_1: C13.1 R13.1 U2.5 | length 164.5
  Top Layer w15: R13.1 1960.14,1061.5 1996.2,1025.44 1996.2,1025.3 2022.99,998.5 C13.1
  Top Layer w25: C13.1 2035.91,992.6 U2.5
NetC14_1: C14.1 D7.1 R10.1 R11.2 U2.4 | length 447.6
  Top Layer w25: R11.2 2126.69,1130 D7.1 2136.69,1108.23 2128.46,1100 ; U2.4 2128.46,1100 ; C14.1 R10.1 2260,1091.02 2254.7,1091.02 2254.7,1095.3 2248.29,1101.71 2176.31,1101.71 2174.59,1100 2128.46,1100
NetC14_2: C14.2 R10.2 TP3.1 U2.1 | length 227.4
  Top Layer w25: U2.1 2254.09,992.6 R10.2 C14.2 ; TP3.1 2300,997.05 2301.46,998.5
NetD1_2: D1.2 D3.2 D6.1 TP18.1 TP19.1 | length 131.7
  Top Layer w25: 1750,900 D6.1
NetD2_3: D2.3 L2.3
NetD2_4: D2.4 L2.2
NetD4_2: D4.2 R5.2 | length 172.7
  Top Layer w30: D4.2 823.5,644.76 823.5,659.86 843.64,680 858.74,680 868.74,690 R5.2
NetD5_2: D5.2 R6.2 | length 50.2
  Top Layer w25: R6.2 D5.2
NetD6_2: D6.2 R12.1 | length 117.2
  Top Layer w25: D6.2 1750,1108.5 1773.8,1084.7 1773.8,1070.42 1789.91,1054.31 1804.19,1054.31 R12.1
NetF1_1: F1.1 J1.2 RV1.1
NetJ1_1: J1.1 RT1.1 RV1.2
NetR1_1: R1.1 R2.2
NetR2_1: R2.1 R3.1
NetR5_1: R5.1 TP14.1 U1.8
NetR6_1: R6.1 R7.2 TP12.1 | length 1140
  Top Layer w25: R7.2 862.99,68.5 R6.1 1243.5,68.5 1280,105 1280,630 1260,650 TP12.1
NetR7_1: R7.1 R8.2 U1.5 | length 357.3
  Top Layer w12: R7.1 800.81,132.31 800.81,200.33 821.42,220.94 831.5,220.94 R8.2
  Top Layer w25: R8.2 831.5,306.5 875,350 U1.5
NetR9_2: R9.2 U1.4 | length 75.8
  Top Layer w25: R9.2 717.72,299.21 U1.4
S-GND: C5.2 C6.2 C7.2 C9.1 C12.1 C13.2 D7.2 R4.1 TP2.1 TP16.1 TP17.1 U2.2 U2.3 | length 172.4
  Top Layer w20: v1(2300,625) R4.1
  Top Layer w50: TP2.1 2025,50 C7.2
  other v1: 2030,490 2080,490 2000,530 2000,575 1890,990 1640,1001.26 1695.91,1040 2150,1040 1695.91,1120 1640,1150 2275,1150

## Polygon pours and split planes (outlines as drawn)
S-GND on Bottom Layer "S-GND_L02_P040" (solid, remove dead copper, pour order 40): 1660,1175 2350,1175 2350,25 1660,25 1660,940 1615,985 1615,1175
GND on Bottom Layer "GND_L02_P028" (solid, remove dead copper, pour order 28): 25,1050 500,1050 570,1120 762.64,1120 1033.4,849.24 1165.76,849.24 1250,765 1250,480 1210,440 1080,440 1020,380 1020,270 890,140 770,140 280,140 240,180 240,190 240,270 200,310 190,310 30,310
NetC1_1 on Bottom Layer "NETC1_1_L02_P018" (solid, remove dead copper, pour order 18): 50,275 175,275 200,250 200,150 250,100 925,100 1075,250 1215,250 1250,215 1250,70 1205,25 75,25 50,50
NetF1_1 on Bottom Layer "NETF1_1_L02_P006" (solid, remove dead copper, pour order 6): 50,2125 25,2100 25,2000 50,1975 300,1975 450,2125 600,2125 625,2125 700,2200 700,2275 675,2300 475,2300 375,2200 300,2200 225,2125 100,2125
NetC4_2 on Bottom Layer "NETC4_2_L02_P004" (solid, remove dead copper, pour order 4): 350,1725 475,1850 500,1875 575,1875 600,1900 600,1950 625,1975 725,1975 750,1950 750,1550 725,1525 700,1500 475,1500 400,1500 350,1550
NetC4_1 on Bottom Layer "NETC4_1_L02_P002" (solid, remove dead copper, pour order 2): 25,1850 100,1925 300,1925 450,2075 550,2075 541.34,2066.34 541.34,1950 475,1950 250,1725 250,1575 175,1500 150,1500 25,1500
S-GND on Top Layer "S-GND_L01_P042" (solid, remove dead copper, pour order 42): 1615,1175 2350,1175 2350,943.67 1675,943.67 1660,943.67 1615,1000
S-GND on Top Layer "S-GND_L01_P000" (solid, remove dead copper, pour order 0): 1975,596.5 2100,596.5 2100,500 2100,470 1975,470
NetC5_1 on Top Layer "NETC5_1_L01_P038" (solid, remove dead copper, pour order 38): 1660,400 1875,400 1920,445 1920,450 1920,575 1931.42,586.42 2100,586.42 2100,928.5 2121.5,950 2225,950 2250,925 2250,850 2275,825 2325,825 2350,800 2350,50 2325,25 1660,25
NetD1_2 on Top Layer "NETD1_2_L01_P036" (solid, remove dead copper, pour order 36): 1660,950 1900,950 1925,925 1935.24,925 2075,925 2075,600 1920,600 1900,580 1900,575 1900,450 1875,425 1660,425
NetR1_1 on Top Layer "NETR1_1_L01_P034" (solid, remove dead copper, pour order 34): 525,975 625,975 625,850 600,825 600,750 575,725 475,725 478.74,728.74 478.74,817.52 511.22,850 525,850 525,875
NetR2_1 on Top Layer "NETR2_1_L01_P032" (solid, remove dead copper, pour order 32): 650,975 825,975 825,853.74 821.26,850 650,850
NetC1_2 on Top Layer "NETC1_2_L01_P030" (solid, remove dead copper, pour order 30): 625,825 850,825 850,975 1000,975 1050,925 1050,750 833.5,750 808.5,725 630.32,725 625,730.32 625,750
GND on Top Layer "GND_L01_P026" (solid, remove dead copper, pour order 26): 540,590 690,590 690,520 691.61,518.39 800,518.39 840,470 840,430 840,400 840,350 800,310 800,203.54 800,20 20,20 20,90 210,90 260,140 260,290 270,300 520,300 540,320 540,340
GND on Top Layer "GND_L01_P024" (solid, remove dead copper, pour order 24): 300,1050 500,1050 500,875 425,800 425,625 300,625
NetR5_1 on Top Layer "NETR5_1_L01_P020" (solid, remove dead copper, pour order 20): 871.46,624.41 871.46,528.54 925,475 1025,475 1100,400 1125,375 1125,325 1200,325 1225,350 1225,450 1200,475 1125,475 975,625
NetC1_1 on Top Layer "NETC1_1_L01_P016" (solid, remove dead copper, pour order 16): 25,425 510,425 510,335 500,325 250,325 225,300 225,150 200,125 25,125
NetC2_1 on Top Layer "NETC2_1_L01_P014" (solid, remove dead copper, pour order 14): 25,1050 250,1050 250,725 250,600 300,550 510,550 510,450 25,450
NetD2_3 on Top Layer "NETD2_3_L01_P012" (solid, remove dead copper, pour order 12): 325,1475 750,1475 750,1225 625,1100 325,1100
NetD2_4 on Top Layer "NETD2_4_L01_P010" (solid, remove dead copper, pour order 10): 25,1475 275,1475 275,1100 25,1100
NetJ1_1 on Top Layer "NETJ1_1_L01_P008" (solid, remove dead copper, pour order 8): 75,2350 50,2350 25,2325 25,2175 50,2150 186.22,2150 200,2150 225,2125 475,2125 575,2025 600,2000 750,2000 775,2025 775,2325 750,2350

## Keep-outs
Keep-Out Layer:
  text ".Layer_Name" at 577,-858.49 h60

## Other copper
Top Layer:
  text ".Layer_Name" at -140,-850 h60
Bottom Layer:
  text ".Layer_Name" at -195,-855 h60

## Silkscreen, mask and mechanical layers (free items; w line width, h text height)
Top Overlay:
  text "PMP30026 Rev_A" at 750,1310 h70 r90
  text "+" at 2320,130 h100
  text "-" at 1940,120 h150
  text ".Layer_Name" at 3965,-855 h60
Bottom Overlay:
  text ".Layer_Name" at 577,-858.49 h60
Top Paste:
  text ".Layer_Name" at 577,-858.49 h60
Bottom Paste:
  text ".Layer_Name" at 577,-858.49 h60
Top Solder:
  text ".Layer_Name" at 577,-858.49 h60
  text ".Layer_Name" at 577,-858.49 h60
Bottom Solder:
  text ".Layer_Name" at 577,-858.49 h60
Drill Guide:
  text ".Layer_Name" at 577,-858.49 h60
M1 Board Outline:
  lines w10: 0,0 0,2370 790,2370 790,1190 2370,1190 2370,0 720,0 0,0
  text ".Layer_Name" at 577,-858.49 h60
M2 Board Dimensions:
  rectangle: 125,-400 500,-275
  rectangle: 0,-275 125,-150
  lines w7: 0,-275 1000,-275 ; 0,-150 0,-400 1000,-400 1000,-150 ; 125,-400 125,-150 ; 250,-400 250,-150 ; 500,-400 500,-150 ; 750,-400 750,-150
  text ".Layer_Name" at 2330,-865 h60
M3 3D STEP Top:
  text ".Layer_Name" at 577,-858.49 h60
M4 3D STEP Bottom:
  text ".Layer_Name" at 577,-858.49 h60
M5 Assembly Top:
  circle w10: c1025,925 r35.36
  lines w10: -292,-930.17 6308,-930.17 ; -292,-726.83 6310,-726.83 ; -292,-523.5 -292,-1133.5 3713,-1133.5 6310,-1133.5 6310,-523.5 -291.5,-523.5 -291.5,-1133.5 1284,-1133.5 ; 2173,-1133.5 2173,-523.5 ; 3440,-726.83 3440,-523.5 ; 4280,-726.83 4280,-523.5 ; 4902,-1140 4902,-937.17 ; 970,40 970,970 1920,970 1920,40 970,40
  text "T1" at 1425,875 h72.83
  text "COMPONENTS MARKED 'DNP' SHOULD NOT BE POPULATED." at 1153.5,-318.5 h60
  text "ASSEMBLY VARIANT:" at 1153,-434 h60
  text ".VariantName" at 2189,-434 h60
  text "PCB VIEWED FROM TOP SIDE" at -228.5,-655.67 h60
  text "BOARD #:" at 2248,-655.67 h60
  text ".PRJ_Number" at 2793.5,-655.67 h60
  text "REV:" at 3638,-655.67 h60
  text ".PCB_Rev" at 3929.5,-655.67 h60
  text "SVN REV:" at 4476,-655.67 h60
  text ".VersionControl_RevNumber" at 4982,-655.67 h60
  text "PLOT NAME =" at -228.5,-1064.34 h60
  text ".plot_File_Name" at 577,-1064.34 h60
  text "GENERATED    :" at 2250,-1064.34 h60
  text ".Print_Date" at 3119.5,-1064.34 h60
  text ".Print_Time" at 3848.5,-1064.34 h60
  text "TEXAS INSTRUMENTS" at 5113,-1064.34 h60
M6 Assembly Bottom:
  lines w10: -292.5,-727.33 6309.5,-727.33 ; -290.5,-930.67 6309.5,-930.67 ; 1115.5,-1140.5 1115.5,-937.67 ; 1737.5,-727.33 1737.5,-524 ; 2577.5,-727.33 2577.5,-524 ; 3844.5,-1134 3844.5,-524 ; 4733.5,-1134 6309,-1134 6309,-524 -292.5,-524 -292.5,-1134 2304.5,-1134 6309.5,-1134 6309.5,-524
  text "COMPONENTS MARKED 'DNP' SHOULD NOT BE POPULATED." at 6102,-318 h60
  text ".VariantName" at 5058,-434 h60
  text "ASSEMBLY VARIANT:" at 6097,-434 h60
  text ".VersionControl_RevNumber" at 1035.5,-656.17 h60
  text "SVN REV:" at 1541.5,-656.17 h60
  text ".PCB_Rev" at 2088,-656.17 h60
  text "REV:" at 2379.5,-656.17 h60
  text ".PRJ_Number" at 3224,-656.17 h60
  text "BOARD #:" at 3769.5,-656.17 h60
  text "PCB VIEWED FROM BOTTOM SIDE" at 6246,-656.17 h60
  text "TEXAS INSTRUMENTS" at 904.5,-1064.84 h60
  text ".Print_Time" at 2169,-1064.84 h60
  text ".Print_Date" at 2898,-1064.84 h60
  text "GENERATED    :" at 3767.5,-1064.84 h60
  text ".plot_File_Name" at 5440.5,-1064.84 h60
  text "PLOT NAME =" at 6246,-1064.84 h60
M9 Title Sheet:
  drawing of 57 lines, arcs and shapes, not listed
  text "1" at 739.84,8036.5 h70
  text "2" at 3235.5,8036.5 h70
  text "3" at 5724.84,8036.5 h70
  text "4" at 8231.51,8036.5 h70
  text "5" at 10730.5,8036.5 h70
  text "6" at 13235.5,8036.5 h70
  text "A" at -416.5,6893.5 h70
  text "A" at 14383.5,6893.5 h70
  text "B" at -416.5,4513.5 h70
  text "B" at 14383.5,4513.5 h70
  text "C" at -416.5,2138.5 h70
  text "C" at 14383.5,2138.5 h70
  text "PROJECT TITLE:" at 11343.5,277.5 h45
  text ".PRJ_Title" at 11393.5,144.17 h70
  text "DESIGNED FOR:" at 11343.5,-23.5 h45
  text ".PRJ_Customer" at 11393.5,-163.5 h70
  text "D" at -416.5,-231.5 h70
  text "D" at 14383.5,-231.5 h70
  text "FILE NAME:" at 11343.5,-323.5 h45
  text ".PCB_File_Name_No_Path" at 11393.5,-443.5 h70
  text "Texas Instruments (TI) and/or its licensors do not warrant the accuracy or completeness of this specification" at 6374,-605.34 h45
  text "ENGINEER:" at 11343.5,-613.5 h45
  text "LAYOUT BY:" at 12848.5,-613.5 h45
  text "or any information contained therein. TI and/or its licensors do not warrant that this design will meet" at 6329.01,-718 h45
  text ".PRJ_Engineer" at 11393.5,-768.49 h70
  text ".PCB_Layout" at 12899,-768.49 h70
  text "the specifications, will be suitable for your application or fit for any particular purpose, or will operate in" at 6329.01,-830.67 h45
  text ".Layer_Name" at 577,-858.49 h60
  text "ALTIUM DESIGNER VERSION:" at 12848.5,-923.5 h45
  text "an implementation. TI and/or its licensors do not warrant that the design is production worthy. You should" at 6329.01,-943.33 h45
  text "completely validate and test your design implementation to confirm the system functionality for your application." at 6374,-1056 h45
  text ".print_Scale" at 11393.5,-1056.83 h70
  text ".Application_BuildNumber" at 12899,-1056.83 h70
  text "1" at 739.84,-1263.5 h70
  text "2" at 3235.5,-1263.5 h70
  text "3" at 5724.84,-1263.5 h70
  text "4" at 8231.51,-1263.5 h70
  text "5" at 10730.5,-1263.5 h70
  text "6" at 13235.5,-1263.5 h70
M10 Fab Notes:
  drawing of 185 lines, arcs and shapes, not listed
  text "DESIGN INFORMATION" at 12381.02,5910 h60
  text "MIN. TRACK WIDTH:" at 11736.46,5730 h60
  text "10" at 12832.7,5730 h60
  text "MIL" at 12987.46,5730 h60
  text "MIN. CLEARANCE:" at 11736.46,5598 h60
  text "0.2" at 12772.7,5598 h60
  text "mm" at 12987.46,5598 h60
  text "MIN. VIA PAD SIZE:" at 11736.46,5466 h60
  text "10" at 12802.71,5466 h60
  text "MIL" at 12987.46,5466 h60
  text "0.05mm (2MIL)" at 12431.46,5324.29 h60
  text "MINIMUM ANNULAR RING" at 11407.23,5320 h60
  text "EXTERNAL" at 13139.46,5320 h60
  text "PER" at 11607.23,5202 h60
  text "IPC-D-275 CLASS 2 LEVEL C" at 11827.23,5202 h60
  text "MIL, HOLES" at 13315.46,5089.71 h60
  text "+/-" at 12923,5089 h60
  text "+/-" at 13777,5089 h60
  text "REGISTRATION TOLERANCES:" at 11407.23,5084 h60
  text "METAL" at 12607,5084 h60
  text "5" at 13183.2,5084 h60
  text "3" at 14016.2,5084 h60
  text "MIL" at 14132.46,5084 h60
  text "MATERIAL:" at 11332.46,4874.54 h60
  text "FR-4 High Tg" at 12318.9,4734.21 h60
  text "X" at 13060,4730 h60
  text "CAM-1" at 13670,4730 h60
  text "FR-408" at 11753.46,4725.64 h60
  text "OTHER" at 13241.46,4725.64 h60
  text "62 MIL (1.6mm) +/-10%" at 12073.56,4562.92 h60
  text "THICKNESS:" at 11407.23,4558.64 h60
  text "X" at 11945.4,4558.64 h60
  text "OTHER" at 13358.46,4558.64 h60
  text "TOLERANCE:" at 11407.23,4400.64 h60
  text "X" at 12246.53,4400.64 h60
  text "ANSI IPC-6012 TYPE 3 CLASS 2" at 12433.48,4400.64 h60
  text "OTHER +/-" at 12433.46,4244.64 h60
  text "BOW & TWIST:" at 11407.23,4087.64 h60
  text "X" at 12246.53,4087.64 h60
  text "ANSI IPC-6012 TYPE 3 CLASS 2" at 12433.48,4087.64 h60
  text "OTHER +/-" at 12433.46,3929.13 h60
  text "DRILLING:" at 11332.46,3790.64 h60
  text "REFERENCE:" at 11407.23,3673.64 h60
  text "X" at 12055.46,3673.64 h60
  text "AS SHOWN" at 12242.46,3673.64 h60
  text "X" at 12956.46,3673.64 h60
  text "NC_DRILL FILES" at 13093.46,3673.64 h60
  text "PTH MIN COPPER THICKNESS:" at 11407.23,3515.64 h60
  text "X" at 12757.46,3515.64 h60
  text "1MIL" at 12894.46,3515.64 h60
  text "OTHER" at 13391.46,3515.64 h60
  text "BOARD FINISH:" at 11332.46,3356.64 h60
  text "SILKSCREEN:" at 11487.68,3238.64 h60
  text "X" at 12436.46,3238.64 h60
  text "TOP" at 12562.46,3238.64 h60
  text "X" at 12946.46,3238.64 h60
  text "BOTTOM" at 13073.46,3238.64 h60
  text "SILKSCREEN COLOR:" at 11487.68,3071.64 h60
  text "X" at 12435.42,3071.64 h60
  text "WHITE" at 12562.46,3071.64 h60
  text "OTHER" at 13073.46,3071.64 h60
  text "SOLDER RESIST COLOR:" at 11487.68,2901.64 h60
  text "X" at 12055.42,2742.44 h60
  text "GREEN" at 12182.46,2742.44 h60
  text "BLUE" at 12773.46,2742.44 h60
  text "OTHER" at 13311.46,2742.44 h60
  text "IMMERSION GOLD (ENIG)" at 12393.46,2553.92 h60
  text "ENEPIG" at 13731,2550.64 h60
  text "SURFACE FINISH:" at 11332.46,2549.64 h60
  text "X" at 11520,2410 h60
  text "IMM. TIN/SILVER OR EQUIV" at 11662,2392.64 h60
  text "OTHER" at 13093.46,2392.64 h60
  text "ARRAY/PANEL:" at 11332.46,2213.64 h60
  text "CUT AND TRIM PER MECH LAYER 1" at 12393.46,2209.35 h60
  text "N.C. ROUTE" at 12393.46,2057.64 h60
  text "X" at 13072.46,2057.64 h60
  text "V. SCORE" at 13259.46,2057.64 h60
  text "CERTIFICATION:" at 11332.46,1920.64 h60
  text "MATERIALS AND WORKMANSHIP FOR ALL PCBS" at 12057.46,1920.64 h60
  text "TO MEET OR EXCEED THE REQUIREMENTS OF:" at 12057.46,1822.64 h60
  text "X" at 11683.96,1686.13 h60
  text "ANSI IPC-A-600F CLASS ->" at 11822.96,1686.13 h60
  text "X" at 13462.02,1686.13 h60
  text "2" at 13580.96,1686.14 h60
  text "1" at 13265.96,1684.64 h60
  text "3" at 13934.96,1684.64 h60
  text "X" at 11686.02,1526.64 h60
  text "UL 94V-0" at 11822.96,1526.64 h60
  text "X" at 12498.02,1526.64 h60
  text "RoHS" at 12634.96,1526.64 h60
  text "OTHER" at 13279.36,1526.64 h60
  text "PER ORDER" at 13676.42,1526.64 h60
  text "ADDITIONAL REQUIREMENTS:" at 11332.46,1385.64 h60
  text "MICROSECTION:" at 11407.23,1270.64 h60
  text "YES" at 12312.96,1270.64 h60
  text "REQUIRED" at 13174.46,1114.49 h60
  text "BARE BOARD ELEC. TEST:" at 11407.23,1111.64 h60
  text "NONE" at 12712.96,1111.64 h60
  text "PER ORDER" at 13766.46,1111.64 h60
  text "X" at 12590,1110 h60
  text "MANUFACTURER'S UL:" at 11407.23,954.64 h60
  text "RAIL" at 12572.96,950.35 h60
  text "METAL" at 13064.77,950.35 h60
  text "X" at 13440,950 h60
  text "SILK" at 13576.46,950.35 h60
  text ".Layer_Name" at 577,-858.49 h60
M11 Gerber Information:
  lines w10: -292,-930.17 6308,-930.17 ; -292,-726.83 6310,-726.83 ; -292,-523.5 -292,-1133.5 3713,-1133.5 6310,-1133.5 6310,-523.5 -291.5,-523.5 -291.5,-1133.5 1284,-1133.5 ; 2173,-1133.5 2173,-523.5 ; 3440,-726.83 3440,-523.5 ; 4280,-726.83 4280,-523.5 ; 4902,-1140 4902,-937.17
  text "ALL ARTWORK VIEWED FROM TOP SIDE" at -228.5,-655.67 h60
  text "BOARD #:" at 2248,-655.67 h60
  text ".PRJ_Number" at 2793.5,-655.67 h60
  text "REV:" at 3638,-655.67 h60
  text ".PCB_Rev" at 3929.5,-655.67 h60
  text "SVN REV:" at 4476,-655.67 h60
  text ".VersionControl_RevNumber" at 4982,-655.67 h60
  text "LAYER NAME =" at -228.5,-858.49 h60
  text "PLOT NAME =" at -228.5,-1064.34 h60
  text ".plot_File_Name" at 577,-1064.34 h60
  text "GENERATED    :" at 2250,-1064.34 h60
  text ".Print_Date" at 3119.5,-1064.34 h60
  text ".Print_Time" at 3848.5,-1064.34 h60
  text "TEXAS INSTRUMENTS" at 5113,-1064.34 h60
M12 Stackup:
  text ".Layer_Name" at 577,-858.49 h60
M13 Component Bodies Top:
  text ".Layer_Name" at 577,-858.49 h60
M14 Component Bodies Bottom:
  text ".Layer_Name" at 577,-858.49 h60
M15 Courtyards Top:
  text ".Layer_Name" at 577,-858.49 h60
M16 Courtyards Bottom:
  text ".Layer_Name" at 577,-858.49 h60
Drill Drawing:
  lines w10: 5536.14,2381.04 5549.97,2381.04 5549.97,2367.21 5577.63,2367.21 5577.63,2381.04 5591.46,2381.04 5591.46,2408.7 5577.63,2408.7 5577.63,2422.52 5549.97,2422.52 5549.97,2408.7 5536.14,2408.7 5536.14,2381.04 ; 5536.14,2505.5 5549.97,2505.5 5549.97,2491.67 5577.63,2491.67 5577.63,2505.5 5591.46,2505.5 5591.46,2533.15 5577.63,2533.15 5577.63,2546.98 5549.97,2546.98 5549.97,2533.15 5536.14,2533.15 5536.14,2505.5 ; 5536.14,2616.13 5563.8,2629.96 5591.46,2616.13 5577.63,2643.78 5591.46,2671.44 5563.8,2657.61 5536.14,2671.44 5549.97,2643.78 5536.14,2616.13 ; 5547.21,2511.03 5555.5,2511.03 5555.5,2502.73 5572.1,2502.73 5572.1,2511.03 5580.39,2511.03 5580.39,2527.62 5572.1,2527.62 5572.1,2535.92 5555.5,2535.92 5555.5,2527.62 5547.21,2527.62 5547.21,2511.03 ; 5547.21,2627.19 5563.8,2635.49 5580.39,2627.19 5572.1,2643.78 5580.39,2660.38 5563.8,2652.08 5547.21,2660.38 5555.5,2643.78 5547.21,2627.19
  lines w12: 5486,2080.95 7465.4,2080.95 ; 5486,3325.54 7465.4,3325.54 ; 5824.17,1956.5 5824.17,3450 ; 6156.28,1956.5 6156.28,3450 ; 6793.29,1956.5 6793.29,3450 ; 7052.64,1956.5 7052.64,3450 ; 5486,1956.5 7465.4,1956.5 7465.4,3450 5486,3450 5486,1956.5
  text "Symbol" at 5560.68,3362.88 h72
  text "Quantity" at 5861.51,3362.88 h72
  text "Finished Hole Size" at 6193.62,3362.88 h72
  text "Plated" at 6830.62,3362.88 h72
  text "Hole Type" at 7089.98,3362.88 h72
  text "37" at 5861.51,3238.42 h60
  text "19.69mil (0.500mm)" at 6193.62,3238.42 h60
  text "PTH" at 6830.62,3238.42 h60
  text "Round" at 7089.98,3238.42 h60
  text "N" at 5535.37,3228.43 h55.31
  text "2" at 5861.51,3113.96 h60
  text "29.53mil (0.750mm)" at 6193.62,3113.96 h60
  text "PTH" at 6830.62,3113.96 h60
  text "Round" at 7089.98,3113.96 h60
  text "L" at 5535.37,3103.97 h55.31
  text "2" at 5861.51,2989.5 h60
  text "31.00mil (0.787mm)" at 6193.62,2989.5 h60
  text "PTH" at 6830.62,2989.5 h60
  text "Round" at 7089.98,2989.5 h60
  text "I" at 5544.58,2979.51 h55.31
  text "2" at 5861.51,2865.04 h60
  text "33.00mil (0.838mm)" at 6193.62,2865.04 h60
  text "PTH" at 6830.62,2865.04 h60
  text "Round" at 7089.98,2865.04 h60
  text "M" at 5535.37,2855.05 h55.31
  text "8" at 5861.51,2740.59 h60
  text "33.46mil (0.850mm)" at 6193.62,2740.59 h60
  text "PTH" at 6830.62,2740.59 h60
  text "Round" at 7089.98,2740.59 h60
  text "B" at 5535.37,2730.59 h55.31
  text "8" at 5861.51,2616.13 h60
  text "35.43mil (0.900mm)" at 6193.62,2616.13 h60
  text "PTH" at 6830.62,2616.13 h60
  text "Round" at 7089.98,2616.13 h60
  text "2" at 5861.51,2491.67 h60
  text "37.40mil (0.950mm)" at 6193.62,2491.67 h60
  text "PTH" at 6830.62,2491.67 h60
  text "Round" at 7089.98,2491.67 h60
  text "11" at 5861.51,2367.21 h60
  text "40.00mil (1.016mm)" at 6193.62,2367.21 h60
  text "PTH" at 6830.62,2367.21 h60
  text "Round" at 7089.98,2367.21 h60
  text "2" at 5861.51,2242.75 h60
  text "41.34mil (1.050mm)" at 6193.62,2242.75 h60
  text "PTH" at 6830.62,2242.75 h60
  text "Round" at 7089.98,2242.75 h60
  text "K" at 5535.37,2232.76 h55.31
  text "2" at 5861.51,2118.29 h60
  text "55.12mil (1.400mm)" at 6193.62,2118.29 h60
  text "PTH" at 6830.62,2118.29 h60
  text "Round" at 7089.98,2118.29 h60
  text "J" at 5535.37,2108.3 h55.31
  text "76 Total" at 5861.51,1993.83 h60
  text ".Layer_Name" at 577,-858.49 h60

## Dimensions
2370,1190 to 2370,0 on M2 Board Dimensions
790,2370 to 790,1190 on M2 Board Dimensions
0,2370 to 790,2370 on M2 Board Dimensions
0,0 to 2370,0 on M2 Board Dimensions
0,-400 to 1000,-400 on M2 Board Dimensions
